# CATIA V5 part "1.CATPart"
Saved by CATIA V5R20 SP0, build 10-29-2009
Part number: Part1
Material "Steel": density 7860 kg/m3, Young's modulus 2e+11 Pa, Poisson ratio 0.266, thermal expansion 1.17e-05 1/K
Bounding box of the stored display mesh (mm): x -130 to 130, y -100 to 100, z -12 to 23
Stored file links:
  E:\Ehsan\Amoozesh\CATIA\CATIA Course\Advanced\Videos\Session-18\1.CATPart
  D:\CATIA V5R20\B20\intel_a\startup\materials\Catalog.CATMaterial
  D:\CATIA V5R20\B20\intel_a\resources\graphic\figures\CATIA_EnvironmentMap_Satin_512x512.jpg
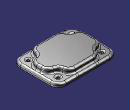
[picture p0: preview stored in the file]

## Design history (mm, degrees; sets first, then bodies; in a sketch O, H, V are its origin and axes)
Set1, material "Steel"
  Extrude1: Element1 Sketch4, Lim1 12, Lim2 0
  Fill1: Boundary Sketch4
  Sketch1 on Fill1, origin (0, 0, 0), H (1, 0, 0), V (0, 1, 0)
    point P1 (-111, 0)
    line L1 (-111, 0) -> (-111, 19.6408)
    point P2 (-111, 19.6408)
    arc A1 centre (-83, 19.6408) radius 28 from (-111, 19.6408) to (-87.4725, 47.2813) cw
    point P4 (-87.4725, 47.2813)
    arc A2 centre (-91.945, 74.9217) radius 28 from (-87.4725, 47.2813) to (-65.9725, 64.4609) ccw
    point P6 (-65.9725, 64.4609)
    arc A3 centre (-40, 54) radius 28 from (-65.9725, 64.4609) to (-40, 82) cw
    point P8 (-40, 82)
    line L2 (-40, 82) -> (40, 82)
    point P9 (40, 82)
    arc A4 centre (40, 54) radius 28 from (40, 82) to (67.4835, 59.3532) cw
    point P11 (67.4835, 59.3532)
    arc A5 centre (94.967, 64.7064) radius 28 from (67.4835, 59.3532) to (88.9835, 37.3532) ccw
    point P13 (88.9835, 37.3532)
    arc A6 centre (83, 10) radius 28 from (88.9835, 37.3532) to (111, 10) cw
    point P15 (111, 10)
    line L3 (111, 10) -> (111, 0)
    point P16 (111, 0)
    reference projected line E1 (95, 97) -> (-95, 97) from Sketch4.L4
    point P17 (111, 0)
    point P18 (111, -10)
    point P19 (88.9835, -37.3532)
    point P20 (67.4835, -59.3532)
    point P21 (40, -82)
    point P22 (-40, -82)
    point P23 (-65.9725, -64.4609)
    point P24 (-87.4725, -47.2813)
    point P25 (-111, -19.6408)
    point P26 (-111, 0)
    arc A7 centre (83, -10) radius 28 from (88.9835, -37.3532) to (111, -10) ccw
    line L4 (111, -10) -> (111, 0)
    arc A8 centre (94.967, -64.7064) radius 28 from (67.4835, -59.3532) to (88.9835, -37.3532) cw
    arc A9 centre (40, -54) radius 28 from (40, -82) to (67.4835, -59.3532) ccw
    line L5 (-40, -82) -> (40, -82)
    arc A10 centre (-40, -54) radius 28 from (-65.9725, -64.4609) to (-40, -82) ccw
    arc A11 centre (-91.945, -74.9217) radius 28 from (-87.4725, -47.2813) to (-65.9725, -64.4609) cw
    arc A12 centre (-83, -19.6408) radius 28 from (-111, -19.6408) to (-87.4725, -47.2813) ccw
    line L6 (-111, 0) -> (-111, -19.6408)
    distance L1 L3 = 222
    radius A6 = 28
    radius A5 = 28
    radius A4 = 28
    radius A1 = 28
    radius A2 = 28
    radius A3 = 28
    length L3 = 10
    distance L2 E1 = 15
    length L2 = 80
    coincidence: P1 H, P16 H
    vertical: L1 V, L3 V
    tangency: A1 L1, A2 A1, A3 A2, A4 L2, A5 A4, A6 A5, A12 L6, A7 L4, A3 L2
    symmetry: L3 L1 V, P9 P8 V, P16 P17 H, P15 P18 H, P13 P19 H, P11 P20 H, P9 P21 H, P8 P22 H, P6 P23 H, P4 P24 H, P2 P25 H, P1 P26 H, A6 A7 H, L3 L4 H, A5 A8 H, A4 A9 H, L2 L5 H, A3 A10 H, A2 A11 H, A1 A12 H, L1 L6 H
  Extrude2: Element1 Sketch1, Lim1 20, Lim2 0
  Fill2: Boundary (edge of Extrude2; edge of Extrude2; edge of Extrude2; edge of Extrude2; edge of Extrude2; edge of Extrude2; edge of Extrude2; edge of Extrude2; edge of Extrude2; edge of Extrude2; edge of Extrude2; edge of Extrude2; edge of Extrude2; edge of Extrude2; edge of Extrude2; edge of Extrude2; edge of Extrude2; edge of Extrude2)
  Split1: ToCut Fill1, Cutting Sketch1
  Sketch2 on Split1, origin (0, 0, 0), H (1, 0, 0), V (0, 1, 0)
    circle A1 centre (95, 65) radius 10
    reference projected arc E1 centre (95, 65) radius 32 from (127, 65) to (95, 97) ccw from edge of Fill1
    circle A2 centre (-95, 65) radius 10
    circle A3 centre (-95, -65) radius 10
    circle A4 centre (95, -65) radius 10
    radius A1 = 10
    concentricity: A1 E1
    symmetry: A1 A2 V, A2 A3 H, A1 A4 H
  Split2: ToCut Split1, Cutting Sketch2
  Extrude3: Element1 Sketch2, Lim1 12, Lim2 0
  Fill3: Boundary edge of Extrude3
  Fill4: Boundary edge of Extrude3
  Fill5: Boundary edge of Extrude3
  Fill6: Boundary edge of Extrude3
  Sketch3 on Fill5, origin (0, 0, -12), H (1, 0, 0), V (0, -1, 0)
    circle A1 centre (95, 65) radius 5
    reference projected circle E1 centre (95, 65) radius 10 from edge of Fill3
    circle A2 centre (-95, 65) radius 5
    circle A3 centre (95, -65) radius 5
    circle A4 centre (-95, -65) radius 5
    radius A1 = 5
    concentricity: A1 E1
    symmetry: A1 A2 V, A1 A3 H, A2 A4 H
  Split3: ToCut Fill6, Cutting Sketch3
  Split4: ToCut Fill5, Cutting Sketch3
  Split5: ToCut Fill3, Cutting Sketch3
  Split6: ToCut Fill4, Cutting Sketch3
  Join1: Elements (Fill2; Extrude2; Split2; Extrude1; Extrude3; Split3; Split4; Split5; Split6)
  Fillet1: radius 6, on face of Fill2
  Fillet2: radius 10, on edge [face of Fill1 | face of Extrude2 from Sketch1.A1]; edge [face of Extrude2 from Sketch1.L2 | face of Fill1]; edge [face of Fill1 | face of Extrude2 from Sketch1.A9]; edge [face of Extrude2 from Sketch1.L3 | face of Fill1]
  Fillet3: radius 6, on edge [face of Fill1 | face of Extrude1 from Sketch4.L2]
  Fillet4: radius 3, on face of Extrude3 from Sketch2.A3; face of Extrude3 from Sketch2.A2; face of Extrude3 from Sketch2.A4; face of Extrude3 from Sketch2.A1
  ThickSurface1: Surface Fillet4, TopOffset 3, BotOffset 0
Body1 (main body)
  Sketch4 on xy-plane, origin (0, 0, 0), H (1, 0, 0), V (0, 1, 0)
    line L1 (127, 65) -> (127, -65)
    line L2 (95, -97) -> (-95, -97)
    line L3 (-127, -65) -> (-127, 65)
    line L4 (-95, 97) -> (95, 97)
    arc A1 centre (95, 65) radius 32 from (127, 65) to (95, 97) ccw
    arc A2 centre (95, -65) radius 32 from (127, -65) to (95, -97) cw
    arc A3 centre (-95, -65) radius 32 from (-95, -97) to (-127, -65) cw
    arc A4 centre (-95, 65) radius 32 from (-127, 65) to (-95, 97) cw
    distance L2 L4 = 194
    distance L1 L3 = 254
    radius A1 = 32
    radius A2 = 32 {= Sketch4.radius(A1)}
    radius A3 = 32 {= Sketch4.radius(A1)}
    radius A4 = 32 {= Sketch4.radius(A1)}
    vertical: L1 V, L3 V
    horizontal: L2 H, L4 H
    equidistance: L1 L3 O, L2 L4 O
    tangency: A1 L1, A1 L4, A2 L1, A2 L2, A3 L2, A3 L3, A4 L3, A4 L4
